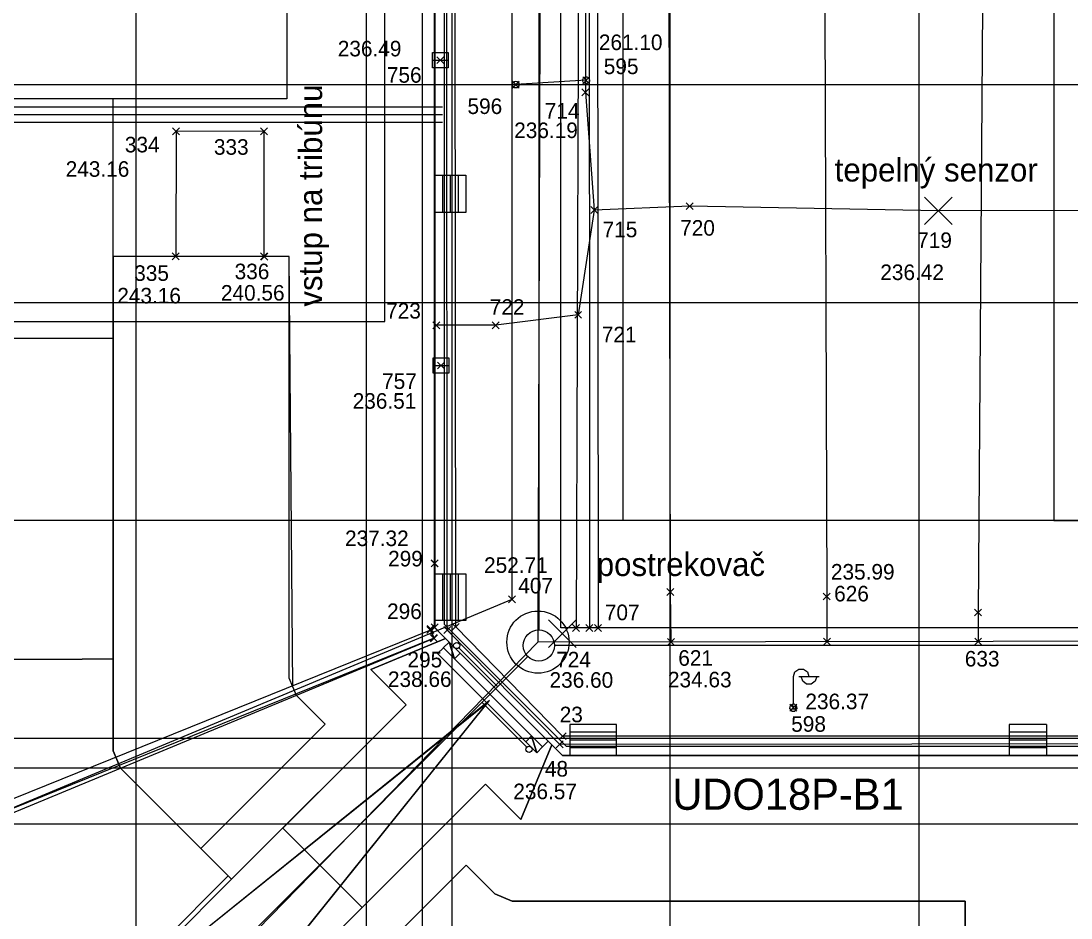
# Model space of a CAD drawing. Extents: x -264205 to -263659, y -1242401 to -1242060.
# Drawn here: x -263905.31 to -263871.58, y -1242229.65 to -1242200.83 of the extents above; entities that cross this region are included whole.
import ezdxf

# ---------------------------------------------------------------- set-up
doc = ezdxf.new("R2010")
doc.units = 0
for name, color, linetype in [('BOD_CISLO', 7, 'Continuous'), ('BOD_SYMBOL', 7, 'Continuous'), ('BOD_VYSKA', 7, 'Continuous'), ('KFA_SO_10-1_DRENAZNY_SYSTEM_IHRISKA', 7, 'Continuous'), ('KFA_SO_10-1_LIZATKA_POMOCNE', 7, 'Continuous'), ('KFA_SO_10-1_OBRUBNIKY_IHRISKO', 7, 'Continuous'), ('KFA_SO_10-1_OHREV', 7, 'Continuous'), ('KFA_SO_10-1_POSTREKOVACE', 7, 'Continuous'), ('KFA_SO_10-1_STRECHY', 7, 'Continuous'), ('KFA_SO_10-1_SVETELNE_VEZE', 7, 'Continuous'), ('KFA_SO_10-1_TEPELNE_SENZORY_A_TRASA', 7, 'Continuous'), ('KFA_SO_10-1_TRIBUNA_A_OBVOD', 7, 'Continuous'), ('KFA_SO_10-1_VPUST_STADION_POKLOP', 7, 'Continuous'), ('KFA_SO_10-1_VSTUPY_TRIBUNA_A', 7, 'Continuous'), ('KFA_SO_10-1_ZABRADLIE_STADION', 7, 'Continuous'), ('KFA_SO_40-2-II_DAZDOVA_KANALIZACIA', 7, 'Continuous'), ('OBRUBNIKY_KOMUNIKACIE_PROJEKT', 7, 'Continuous'), ('OSI_STAVBY_KFA', 7, 'Continuous'), ('POPIS', 7, 'Continuous'), ('SITUACIA_DSP_2D', 7, 'Continuous')]:
    doc.layers.add(name, color=color, linetype=linetype)

msp = doc.modelspace()

# ---------------------------------------------------------------- linework, layer by layer
at = {"layer": 'BOD_SYMBOL'}
for p, q in [((-263891.948, -1242202.198), (-263891.726, -1242201.977)), ((-263891.726, -1242202.198), (-263891.948, -1242201.977)), ((-263887.264, -1242202.843), (-263887.043, -1242202.622)), ((-263887.043, -1242202.843), (-263887.264, -1242202.622)), ((-263889.522, -1242202.982), (-263889.301, -1242202.762)), ((-263889.301, -1242202.982), (-263889.522, -1242202.762)), ((-263887.288, -1242203.227), (-263887.067, -1242203.005)), ((-263887.067, -1242203.227), (-263887.288, -1242203.005)), ((-263900.44, -1242204.48), (-263900.219, -1242204.258)), ((-263900.219, -1242204.48), (-263900.44, -1242204.258)), ((-263897.612, -1242204.482), (-263897.391, -1242204.262)), ((-263897.391, -1242204.482), (-263897.612, -1242204.262)), ((-263897.611, -1242204.484), (-263897.389, -1242204.262)), ((-263897.389, -1242204.484), (-263897.611, -1242204.262)), ((-263883.936, -1242206.889), (-263883.715, -1242206.667)), ((-263883.715, -1242206.889), (-263883.936, -1242206.667)), ((-263887.003, -1242207.012), (-263886.781, -1242206.791)), ((-263886.781, -1242207.012), (-263887.003, -1242206.791)), ((-263875.948, -1242207.035), (-263875.726, -1242206.815)), ((-263875.726, -1242207.035), (-263875.948, -1242206.815)), ((-263900.451, -1242208.499), (-263900.23, -1242208.279)), ((-263900.23, -1242208.499), (-263900.451, -1242208.279)), ((-263897.611, -1242208.498), (-263897.39, -1242208.278)), ((-263897.39, -1242208.498), (-263897.611, -1242208.278)), ((-263897.603, -1242208.508), (-263897.382, -1242208.288)), ((-263897.382, -1242208.508), (-263897.603, -1242208.288)), ((-263887.52, -1242210.377), (-263887.299, -1242210.157)), ((-263887.299, -1242210.377), (-263887.52, -1242210.157)), ((-263892.079, -1242210.715), (-263891.857, -1242210.494)), ((-263891.857, -1242210.715), (-263892.079, -1242210.494)), ((-263890.169, -1242210.715), (-263889.948, -1242210.494)), ((-263889.948, -1242210.715), (-263890.169, -1242210.494)), ((-263891.927, -1242212.008), (-263891.706, -1242211.786)), ((-263891.706, -1242212.008), (-263891.927, -1242211.786)), ((-263892.137, -1242218.37), (-263891.916, -1242218.149)), ((-263891.916, -1242218.37), (-263892.137, -1242218.149)), ((-263892.133, -1242218.369), (-263891.911, -1242218.147)), ((-263891.911, -1242218.369), (-263892.133, -1242218.147)), ((-263884.561, -1242219.285), (-263884.34, -1242219.063)), ((-263884.34, -1242219.285), (-263884.561, -1242219.063)), ((-263879.536, -1242219.431), (-263879.315, -1242219.211)), ((-263879.315, -1242219.431), (-263879.536, -1242219.211)), ((-263889.644, -1242219.522), (-263889.422, -1242219.301)), ((-263889.422, -1242219.522), (-263889.644, -1242219.301)), ((-263874.676, -1242219.944), (-263874.454, -1242219.724)), ((-263874.454, -1242219.944), (-263874.676, -1242219.724)), ((-263892.264, -1242220.478), (-263892.043, -1242220.257)), ((-263892.043, -1242220.478), (-263892.264, -1242220.257)), ((-263892.133, -1242220.421), (-263891.912, -1242220.201)), ((-263891.912, -1242220.421), (-263892.133, -1242220.201)), ((-263891.454, -1242220.407), (-263891.233, -1242220.186)), ((-263891.233, -1242220.407), (-263891.454, -1242220.186)), ((-263887.587, -1242220.441), (-263887.366, -1242220.22)), ((-263887.366, -1242220.441), (-263887.587, -1242220.22)), ((-263887.159, -1242220.441), (-263886.938, -1242220.22)), ((-263886.938, -1242220.441), (-263887.159, -1242220.22)), ((-263886.881, -1242220.441), (-263886.66, -1242220.22)), ((-263886.66, -1242220.441), (-263886.881, -1242220.22)), ((-263892.269, -1242220.508), (-263892.049, -1242220.286)), ((-263892.049, -1242220.508), (-263892.269, -1242220.286)), ((-263892.166, -1242220.768), (-263891.944, -1242220.546)), ((-263891.944, -1242220.768), (-263892.166, -1242220.546)), ((-263892.149, -1242220.772), (-263891.928, -1242220.551)), ((-263891.928, -1242220.772), (-263892.149, -1242220.551)), ((-263891.724, -1242220.508), (-263891.503, -1242220.288)), ((-263891.503, -1242220.508), (-263891.724, -1242220.288)), ((-263888.028, -1242220.627), (-263887.807, -1242220.407)), ((-263887.807, -1242220.627), (-263888.028, -1242220.407)), ((-263884.539, -1242220.89), (-263884.318, -1242220.67)), ((-263884.318, -1242220.89), (-263884.539, -1242220.67)), ((-263879.529, -1242220.883), (-263879.307, -1242220.663)), ((-263879.307, -1242220.883), (-263879.529, -1242220.663)), ((-263874.671, -1242220.877), (-263874.45, -1242220.657)), ((-263874.45, -1242220.877), (-263874.671, -1242220.657)), ((-263880.606, -1242223.005), (-263880.385, -1242222.785)), ((-263880.385, -1242223.005), (-263880.606, -1242222.785)), ((-263888.115, -1242224.181), (-263887.894, -1242223.961)), ((-263887.894, -1242224.181), (-263888.115, -1242223.961)), ((-263888.019, -1242223.917), (-263887.799, -1242223.697)), ((-263887.799, -1242223.917), (-263888.019, -1242223.697))]:
    msp.add_line(p, q, dxfattribs=at)
at = {"layer": 'KFA_SO_10-1_DRENAZNY_SYSTEM_IHRISKA'}
for p, q in [((-263884.45, -1242219.174), (-263884.428, -1242220.78)), ((-263879.426, -1242219.321), (-263879.418, -1242220.773)), ((-263874.565, -1242219.834), (-263874.561, -1242220.767))]:
    msp.add_line(p, q, dxfattribs=at)
for points in [[(-263884.503, -1242110.771), (-263884.575, -1242164.194), (-263884.45, -1242219.174)], [(-263874.484, -1242165.197), (-263874.412, -1242198.851), (-263874.565, -1242219.834)], [(-263879.285, -1242166.044), (-263879.493, -1242197.351), (-263879.426, -1242219.321)]]:
    msp.add_lwpolyline(points, dxfattribs=at)
at = {"layer": 'KFA_SO_10-1_LIZATKA_POMOCNE'}
msp.add_line((-263887.154, -1242202.732), (-263889.411, -1242202.872), dxfattribs=at)
for centre, major_axis, ratio in [((-263887.154, -1242202.732), (-0.019, 0.11), 0.966689), ((-263889.411, -1242202.872), (-0.002, 0.107), 0.988325)]:
    msp.add_ellipse(centre, major_axis=major_axis, ratio=ratio, dxfattribs=at)
at = {"layer": 'KFA_SO_10-1_OBRUBNIKY_IHRISKO'}
for points in [[(-263891.613, -1242220.398), (-263891.628, -1242199.847), (-263891.619, -1242183.131)], [(-263891.344, -1242220.296), (-263891.365, -1242199.823), (-263891.369, -1242183.262)], [(-263812.296, -1242220.436), (-263815.955, -1242224.08), (-263837.958, -1242224.073), (-263865.382, -1242224.053), (-263888.004, -1242224.071), (-263891.613, -1242220.398)], [(-263812.557, -1242220.31), (-263816.064, -1242223.83), (-263837.963, -1242223.813), (-263865.333, -1242223.805), (-263887.909, -1242223.807), (-263891.344, -1242220.296)]]:
    msp.add_lwpolyline(points, dxfattribs=at)
at = {"layer": 'KFA_SO_10-1_OHREV'}
for points in [[(-263887.153, -1242108.434), (-263887.285, -1242164.665), (-263887.476, -1242220.33)], [(-263886.925, -1242108.434), (-263887.067, -1242164.606), (-263887.048, -1242220.33)], [(-263886.653, -1242108.434), (-263886.821, -1242164.626), (-263886.77, -1242220.33)]]:
    msp.add_lwpolyline(points, dxfattribs=at)
at = {"layer": 'KFA_SO_10-1_POSTREKOVACE'}
for p, q in [((-263888.359, -1242220.959), (-263887.475, -1242220.075)), ((-263887.475, -1242220.959), (-263888.359, -1242220.075))]:
    msp.add_line(p, q, dxfattribs=at)
at = {"layer": 'KFA_SO_10-1_STRECHY'}
msp.add_line((-263889.533, -1242219.411), (-263889.511, -1242109.378), dxfattribs=at)
msp.add_lwpolyline([(-263912.101, -1242228.742), (-263908.157, -1242227.179), (-263889.533, -1242219.411)], dxfattribs=at)
at = {"layer": 'KFA_SO_10-1_SVETELNE_VEZE'}
for p, q in [((-263880.321, -1242221.895), (-263879.671, -1242221.895)), ((-263880.496, -1242222.895), (-263880.496, -1242222.895))]:
    msp.add_line(p, q, dxfattribs=at)
for points in [[(-263880.558, -1242222.933), (-263880.421, -1242222.933), (-263880.421, -1242222.857), (-263880.558, -1242222.857), (-263880.496, -1242222.77), (-263880.596, -1242222.82), (-263880.621, -1242222.92), (-263880.546, -1242223.008), (-263880.446, -1242223.008), (-263880.371, -1242222.92), (-263880.396, -1242222.82), (-263880.496, -1242222.77), (-263880.496, -1242221.895), (-263880.446, -1242221.745), (-263880.321, -1242221.657), (-263880.171, -1242221.657), (-263880.046, -1242221.745), (-263879.996, -1242221.895)], [(-263879.746, -1242221.895), (-263879.796, -1242222.045), (-263879.921, -1242222.133), (-263880.071, -1242222.133), (-263880.196, -1242222.045), (-263880.246, -1242221.895)]]:
    msp.add_lwpolyline(points, dxfattribs=at)
at = {"layer": 'KFA_SO_10-1_TEPELNE_SENZORY_A_TRASA'}
for p, q in [((-263876.279, -1242207.367), (-263875.395, -1242206.483)), ((-263875.395, -1242207.367), (-263876.279, -1242206.483)), ((-263890.058, -1242210.604), (-263891.968, -1242210.604))]:
    msp.add_line(p, q, dxfattribs=at)
for points in [[(-263827.921, -1242121.921), (-263875.963, -1242121.979), (-263885.626, -1242121.792), (-263887.003, -1242121.689), (-263887.052, -1242145.021), (-263887.18, -1242173.77), (-263887.177, -1242203.116), (-263886.892, -1242206.901)], [(-263828.041, -1242206.742), (-263835.117, -1242206.806), (-263859.991, -1242206.899), (-263875.837, -1242206.925), (-263883.825, -1242206.778), (-263886.892, -1242206.901), (-263887.41, -1242210.267), (-263890.058, -1242210.604)]]:
    msp.add_lwpolyline(points, dxfattribs=at)
at = {"layer": 'KFA_SO_10-1_TRIBUNA_A_OBVOD'}
msp.add_line((-263908.657, -1242227.545), (-263892.039, -1242220.661), dxfattribs=at)
msp.add_lwpolyline([(-263892.039, -1242220.661), (-263892.154, -1242220.367), (-263892.023, -1242220.311), (-263892.026, -1242218.259), (-263892.022, -1242218.258), (-263892.014, -1242181.432), (-263893.611, -1242181.428), (-263893.622, -1242166.388), (-263895.226, -1242166.39), (-263895.226, -1242162.375), (-263893.627, -1242162.368), (-263893.627, -1242147.332), (-263892.023, -1242147.335), (-263892.008, -1242110.521), (-263892.009, -1242110.521), (-263892.017, -1242108.459), (-263892.149, -1242108.408), (-263892.034, -1242108.1)], dxfattribs=at)
at = {"layer": 'KFA_SO_10-1_VPUST_STADION_POKLOP'}
for p, q in [((-263891.837, -1242202.087), (-263891.837, -1242202.087)), ((-263891.817, -1242211.897), (-263891.817, -1242211.897))]:
    msp.add_line(p, q, dxfattribs=at)
for points in [[(-263892.087, -1242202.087), (-263892.087, -1242201.837), (-263891.587, -1242201.837), (-263891.587, -1242202.337), (-263892.087, -1242202.337), (-263892.087, -1242202.087), (-263891.587, -1242202.087)], [(-263892.067, -1242211.897), (-263892.067, -1242211.647), (-263891.567, -1242211.647), (-263891.567, -1242212.147), (-263892.067, -1242212.147), (-263892.067, -1242211.897), (-263891.567, -1242211.897)]]:
    msp.add_lwpolyline(points, dxfattribs=at)
at = {"layer": 'KFA_SO_10-1_VSTUPY_TRIBUNA_A'}
msp.add_line((-263897.501, -1242208.388), (-263897.502, -1242204.372), dxfattribs=at)
msp.add_lwpolyline([(-263897.502, -1242204.372), (-263897.5, -1242204.373), (-263900.329, -1242204.369), (-263900.34, -1242208.389), (-263897.492, -1242208.398), (-263897.501, -1242208.388)], dxfattribs=at)
at = {"layer": 'KFA_SO_10-1_ZABRADLIE_STADION'}
for p, q in [((-263892.159, -1242220.397), (-263908.194, -1242226.884)), ((-263892.055, -1242220.657), (-263892.159, -1242220.397)), ((-263908.089, -1242227.144), (-263892.055, -1242220.657))]:
    msp.add_line(p, q, dxfattribs=at)
at = {"layer": 'KFA_SO_40-2-II_DAZDOVA_KANALIZACIA'}
for points in [[(-263814.907, -1242107.856), (-263815.198, -1242164.443), (-263815.189, -1242220.791), (-263852.152, -1242220.736), (-263888.701, -1242220.786), (-263906.731, -1242239.259)], [(-263814.907, -1242107.856), (-263851.887, -1242107.945), (-263888.606, -1242107.773), (-263888.523, -1242164.395), (-263888.701, -1242220.786)]]:
    msp.add_lwpolyline(points, dxfattribs=at)
msp.add_circle((-263888.701, -1242220.786), 1, dxfattribs=at)
at = {"layer": 'OBRUBNIKY_KOMUNIKACIE_PROJEKT'}
for p, q in [((-263902.343, -1242203.332), (-263909.043, -1242203.332)), ((-263902.343, -1242224.282), (-263902.343, -1242203.332)), ((-263891.673, -1242220.675), (-263894.073, -1242221.669)), ((-263888.26, -1242224.088), (-263891.673, -1242220.675)), ((-263894.073, -1242221.669), (-263892.937, -1242222.806)), ((-263890.254, -1242222.659), (-263903.277, -1242233.148)), ((-263900.731, -1242235.694), (-263890.254, -1242222.659)), ((-263892.937, -1242222.806), (-263898.544, -1242228.407)), ((-263902.112, -1242224.837), (-263902.343, -1242224.282)), ((-263889.254, -1242226.488), (-263888.26, -1242224.088)), ((-263898.543, -1242228.407), (-263902.112, -1242224.837)), ((-263895.995, -1242230.956), (-263890.391, -1242225.352)), ((-263890.391, -1242225.352), (-263889.254, -1242226.488)), ((-263898.65, -1242228.301), (-263903.39, -1242233.035)), ((-263898.544, -1242228.407), (-263903.281, -1242233.144))]:
    msp.add_line(p, q, dxfattribs=at)
at = {"layer": 'OSI_STAVBY_KFA'}
for p, q in [((-263901.618, -1242083.237), (-263901.618, -1242246.707)), ((-263894.218, -1242083.237), (-263894.218, -1242246.707)), ((-263892.418, -1242083.237), (-263892.418, -1242246.707)), ((-263891.468, -1242083.237), (-263891.468, -1242246.707)), ((-263884.468, -1242083.237), (-263884.468, -1242246.707)), ((-263876.468, -1242083.237), (-263876.468, -1242246.707)), ((-263792.653, -1242202.882), (-263909.343, -1242202.882)), ((-263792.653, -1242209.882), (-263909.343, -1242209.882)), ((-263792.653, -1242216.882), (-263911.523, -1242216.882)), ((-263792.653, -1242223.882), (-263911.523, -1242223.882)), ((-263792.653, -1242224.832), (-263911.523, -1242224.832)), ((-263792.653, -1242226.632), (-263911.523, -1242226.632))]:
    msp.add_line(p, q, dxfattribs=at)
at = {"layer": 'SITUACIA_DSP_2D'}
for p, q in [((-263887.968, -1242220.33), (-263887.968, -1242108.434)), ((-263885.968, -1242216.882), (-263885.968, -1242111.882)), ((-263888.673, -1242164.687), (-263888.673, -1242220.396)), ((-263893.618, -1242210.482), (-263893.618, -1242166.382)), ((-263892.018, -1242220.33), (-263892.018, -1242181.432)), ((-263892.018, -1242181.432), (-263892.018, -1242220.33)), ((-263891.718, -1242181.132), (-263891.718, -1242220.206)), ((-263896.768, -1242181.582), (-263896.768, -1242203.332)), ((-263872.128, -1242200.382), (-263872.128, -1242216.882)), ((-263896.768, -1242203.332), (-263909.118, -1242203.332)), ((-263902.343, -1242203.332), (-263909.043, -1242203.332)), ((-263902.343, -1242224.282), (-263902.343, -1242203.332)), ((-263910.004, -1242203.582), (-263891.768, -1242203.582)), ((-263910.108, -1242203.832), (-263891.768, -1242203.832)), ((-263910.211, -1242204.082), (-263891.768, -1242204.082)), ((-263892.018, -1242205.783), (-263891.018, -1242205.783)), ((-263891.768, -1242205.783), (-263891.768, -1242206.981)), ((-263891.518, -1242205.783), (-263891.518, -1242206.981)), ((-263891.268, -1242205.783), (-263891.268, -1242206.981)), ((-263891.018, -1242205.783), (-263891.018, -1242206.981)), ((-263891.018, -1242206.981), (-263892.018, -1242206.981)), ((-263902.343, -1242208.394), (-263902.343, -1242224.282)), ((-263896.693, -1242208.394), (-263902.343, -1242208.394)), ((-263896.693, -1242208.394), (-263902.343, -1242208.394)), ((-263902.343, -1242208.394), (-263902.343, -1242224.282)), ((-263896.578, -1242222.219), (-263896.693, -1242208.394)), ((-263896.693, -1242221.942), (-263896.693, -1242208.394)), ((-263914.293, -1242210.482), (-263893.618, -1242210.482)), ((-263903.343, -1242211.032), (-263921.351, -1242211.032)), ((-263902.343, -1242211.032), (-263903.343, -1242211.032)), ((-263817.968, -1242216.882), (-263885.968, -1242216.882)), ((-263872.128, -1242216.882), (-263831.808, -1242216.882)), ((-263892.018, -1242218.593), (-263891.018, -1242218.593)), ((-263891.768, -1242218.593), (-263891.768, -1242220.091)), ((-263891.518, -1242218.593), (-263891.518, -1242220.091)), ((-263891.268, -1242218.593), (-263891.268, -1242220.091)), ((-263891.018, -1242218.593), (-263891.018, -1242220.091)), ((-263891.018, -1242220.091), (-263892.018, -1242220.091)), ((-263891.718, -1242220.206), (-263887.792, -1242224.132)), ((-263891.673, -1242220.675), (-263892.018, -1242220.33)), ((-263892.018, -1242220.33), (-263887.916, -1242224.432)), ((-263815.968, -1242220.33), (-263887.968, -1242220.33)), ((-263894.073, -1242221.669), (-263891.673, -1242220.675)), ((-263891.673, -1242220.675), (-263894.073, -1242221.669)), ((-263891.742, -1242220.974), (-263891.558, -1242220.79)), ((-263888.26, -1242224.088), (-263891.673, -1242220.675)), ((-263891.558, -1242220.79), (-263891.204, -1242221.144)), ((-263888.376, -1242223.973), (-263891.558, -1242220.79)), ((-263891.387, -1242221.326), (-263891.558, -1242220.79)), ((-263852.268, -1242220.896), (-263888.173, -1242220.896)), ((-263889.023, -1242221.253), (-263906.365, -1242238.596)), ((-263891.924, -1242221.157), (-263891.74, -1242220.973)), ((-263891.924, -1242221.157), (-263888.742, -1242224.339)), ((-263888.558, -1242224.155), (-263891.74, -1242220.973)), ((-263891.388, -1242221.328), (-263891.204, -1242221.144)), ((-263891.24, -1242220.967), (-263889.988, -1242222.219)), ((-263923.393, -1242221.332), (-263903.343, -1242221.332)), ((-263902.343, -1242221.332), (-263903.343, -1242221.332)), ((-263896.463, -1242222.496), (-263896.693, -1242221.942)), ((-263892.937, -1242222.806), (-263894.073, -1242221.669)), ((-263894.073, -1242221.669), (-263892.937, -1242222.806)), ((-263896.463, -1242222.496), (-263896.578, -1242222.219)), ((-263895.535, -1242223.424), (-263896.463, -1242222.496)), ((-263895.535, -1242223.424), (-263896.463, -1242222.496)), ((-263890.333, -1242222.748), (-263903.277, -1242233.148)), ((-263900.731, -1242235.694), (-263890.333, -1242222.748)), ((-263892.937, -1242222.806), (-263898.544, -1242228.407)), ((-263896.896, -1242226.765), (-263892.937, -1242222.806)), ((-263889.059, -1242224.16), (-263890.494, -1242222.725)), ((-263899.53, -1242227.419), (-263895.535, -1242223.424)), ((-263899.53, -1242227.419), (-263895.535, -1242223.424)), ((-263886.179, -1242223.432), (-263887.677, -1242223.432)), ((-263887.677, -1242223.432), (-263887.677, -1242224.432)), ((-263886.179, -1242224.432), (-263886.179, -1242223.432)), ((-263872.369, -1242223.432), (-263873.567, -1242223.432)), ((-263873.567, -1242223.432), (-263873.567, -1242224.432)), ((-263872.369, -1242223.432), (-263872.369, -1242224.432)), ((-263889.096, -1242223.985), (-263888.912, -1242223.801)), ((-263888.742, -1242224.339), (-263888.912, -1242223.801)), ((-263886.179, -1242223.682), (-263887.677, -1242223.682)), ((-263886.179, -1242223.932), (-263887.677, -1242223.932)), ((-263872.369, -1242223.682), (-263873.567, -1242223.682)), ((-263872.369, -1242223.932), (-263873.567, -1242223.932)), ((-263902.343, -1242224.282), (-263902.113, -1242224.837)), ((-263902.343, -1242224.282), (-263902.113, -1242224.837)), ((-263902.112, -1242224.837), (-263902.343, -1242224.282)), ((-263888.26, -1242224.088), (-263889.254, -1242226.488)), ((-263889.254, -1242226.488), (-263888.26, -1242224.088)), ((-263888.742, -1242224.339), (-263888.558, -1242224.155)), ((-263888.56, -1242224.156), (-263888.376, -1242223.973)), ((-263887.916, -1242224.432), (-263888.26, -1242224.088)), ((-263887.792, -1242224.132), (-263816.144, -1242224.132)), ((-263886.179, -1242224.182), (-263887.677, -1242224.182)), ((-263872.369, -1242224.182), (-263873.567, -1242224.182)), ((-263816.02, -1242224.432), (-263887.916, -1242224.432)), ((-263887.916, -1242224.432), (-263816.02, -1242224.432)), ((-263902.113, -1242224.837), (-263899.53, -1242227.419)), ((-263902.113, -1242224.837), (-263899.53, -1242227.419)), ((-263898.543, -1242228.407), (-263902.112, -1242224.837)), ((-263895.995, -1242230.956), (-263890.391, -1242225.352)), ((-263890.391, -1242225.351), (-263894.351, -1242229.311)), ((-263889.254, -1242226.488), (-263890.391, -1242225.351)), ((-263890.391, -1242225.352), (-263889.254, -1242226.488)), ((-263894.351, -1242229.311), (-263896.896, -1242226.765)), ((-263895.005, -1242231.945), (-263891.01, -1242227.95)), ((-263891.01, -1242227.95), (-263895.005, -1242231.945)), ((-263891.01, -1242227.95), (-263890.082, -1242228.878)), ((-263890.082, -1242228.878), (-263891.01, -1242227.95)), ((-263898.65, -1242228.301), (-263903.39, -1242233.035)), ((-263898.544, -1242228.407), (-263903.281, -1242233.144)), ((-263890.082, -1242228.878), (-263889.528, -1242229.107)), ((-263889.528, -1242229.107), (-263890.082, -1242228.878)), ((-263889.528, -1242229.107), (-263874.98, -1242229.107)), ((-263874.98, -1242229.107), (-263889.528, -1242229.107)), ((-263874.98, -1242229.107), (-263874.98, -1242234.757)), ((-263874.98, -1242234.757), (-263874.98, -1242229.107))]:
    msp.add_line(p, q, dxfattribs=at)
for points in [[(-263891.558, -1242220.79), (-263891.387, -1242221.326), (-263891.204, -1242221.144)], [(-263888.742, -1242224.339), (-263888.558, -1242224.155), (-263888.912, -1242223.801)]]:
    msp.add_lwpolyline(points, close=True, dxfattribs=at)
for centre, radius in [((-263888.673, -1242220.896), 0.5), ((-263891.31, -1242220.896), 0.1), ((-263888.988, -1242224.231), 0.1)]:
    msp.add_circle(centre, radius, dxfattribs=at)

# ---------------------------------------------------------------- texts
at = {"layer": 'BOD_CISLO'}
for s, p in [('595', (-263886.587, -1242202.533)), ('756', (-263893.555, -1242202.81)), ('596', (-263890.965, -1242203.816)), ('714', (-263888.484, -1242203.964)), ('334', (-263901.973, -1242205.049)), ('333', (-263899.112, -1242205.125)), ('715', (-263886.625, -1242207.777)), ('720', (-263884.133, -1242207.725)), ('719', (-263876.519, -1242208.12)), ('335', (-263901.672, -1242209.178)), ('336', (-263898.446, -1242209.125)), ('722', (-263890.251, -1242210.268)), ('723', (-263893.579, -1242210.389)), ('721', (-263886.651, -1242211.151)), ('757', (-263893.709, -1242212.651)), ('299', (-263893.516, -1242218.353)), ('407', (-263889.334, -1242219.221)), ('626', (-263879.186, -1242219.478)), ('296', (-263893.549, -1242220.044)), ('707', (-263886.553, -1242220.081)), ('295', (-263892.894, -1242221.598)), ('724', (-263888.118, -1242221.598)), ('621', (-263884.194, -1242221.546)), ('633', (-263874.989, -1242221.571)), ('23', (-263888.003, -1242223.361)), ('598', (-263880.566, -1242223.667)), ('48', (-263888.479, -1242225.106))]:
    msp.add_text(s, height=0.5, dxfattribs=at).set_placement(p)
at = {"layer": 'BOD_VYSKA'}
for s, p in [('261.10', (-263886.745, -1242201.761)), ('236.49', (-263895.133, -1242201.964)), ('236.19', (-263889.465, -1242204.589)), ('243.16', (-263903.874, -1242205.833)), ('236.42', (-263877.704, -1242209.151)), ('243.16', (-263902.216, -1242209.902)), ('240.56', (-263898.886, -1242209.812)), ('236.51', (-263894.654, -1242213.286)), ('237.32', (-263894.9, -1242217.7)), ('252.71', (-263890.433, -1242218.561)), ('235.99', (-263879.29, -1242218.776)), ('238.66', (-263893.521, -1242222.227)), ('236.60', (-263888.329, -1242222.252)), ('234.63', (-263884.526, -1242222.239)), ('236.37', (-263880.11, -1242222.942)), ('236.57', (-263889.494, -1242225.834))]:
    msp.add_text(s, height=0.5, dxfattribs=at).set_placement(p)
at = {"layer": 'KFA_SO_10-1_SVETELNE_VEZE'}
msp.add_text('UDO18P-B1', height=1, dxfattribs=at).set_placement((-263884.385, -1242226.174))
at = {"layer": 'POPIS'}
msp.add_text('vstup na tribúnu', height=0.75, rotation=90, dxfattribs=at).set_placement((-263895.636, -1242210.006))
for s, p in [('tepelný senzor', (-263879.169, -1242205.985)), ('postrekovač', (-263886.813, -1242218.662))]:
    msp.add_text(s, height=0.75, dxfattribs=at).set_placement(p)

doc.saveas('drawing.dxf')
